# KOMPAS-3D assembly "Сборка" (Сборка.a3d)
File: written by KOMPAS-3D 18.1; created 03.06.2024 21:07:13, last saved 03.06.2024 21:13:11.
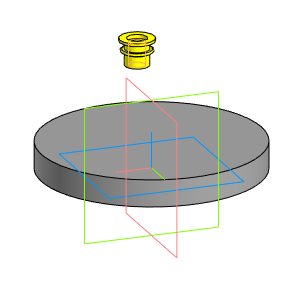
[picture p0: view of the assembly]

Document properties: Полное имя файла: C:\Users\root\Desktop\Новая папка\тест\Сборка.a3d

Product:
- Part/product: Сборка
    Масса: 0.418979
  - Component [libComponent]: Заклепка гаечная / ТУ 1680-001-30391216-2011 С С-М6х15,5-S  | Масса: 0.0041025; Раздел спецификации: Прочие изделия; source file: ..\..\..\..\..\Библиотека v0.1\Библиотека.kle|Заклепка гаечная ТУ 1680-001-30391216-2011 С С-М6х15,5-S.m3d
  - Component [detail]: Деталь  | Масса: 0.414877; source file: Деталь.m3d

Referenced files in C:\Users\root\Desktop\Новая папка\тест\: Деталь.m3d
Referenced files in C:\Библиотека v0.1\: Библиотека.kle
Referenced files: Заклепка гаечная ТУ 1680-001-30391216-2011 С С-М6х15,5-S.m3d
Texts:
  Заклепка гаечная ТУ 1680-001-30391216-2011 С С-М6х15,5-S  (1)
